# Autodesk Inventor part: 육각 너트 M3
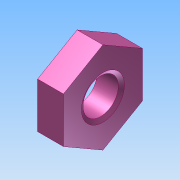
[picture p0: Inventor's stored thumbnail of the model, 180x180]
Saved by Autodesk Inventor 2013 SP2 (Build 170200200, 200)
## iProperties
Created: 2025-09
Part Number: 육각 너트 M3
Material: Generic
Document SubType Name: Modeling
Designer: a
Density: 1 g/cm^3
Author: a
변환 표준: STEP AP214IS
전처리기: Build: 200, Release: 2013 SP2 Update 6 - Date: Thu 07/17/2014
전송 단위: 밀리미터
불확실성: 0.01
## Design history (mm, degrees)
node "육각 너트 M31"
body "Solid1"
node "기준1"
